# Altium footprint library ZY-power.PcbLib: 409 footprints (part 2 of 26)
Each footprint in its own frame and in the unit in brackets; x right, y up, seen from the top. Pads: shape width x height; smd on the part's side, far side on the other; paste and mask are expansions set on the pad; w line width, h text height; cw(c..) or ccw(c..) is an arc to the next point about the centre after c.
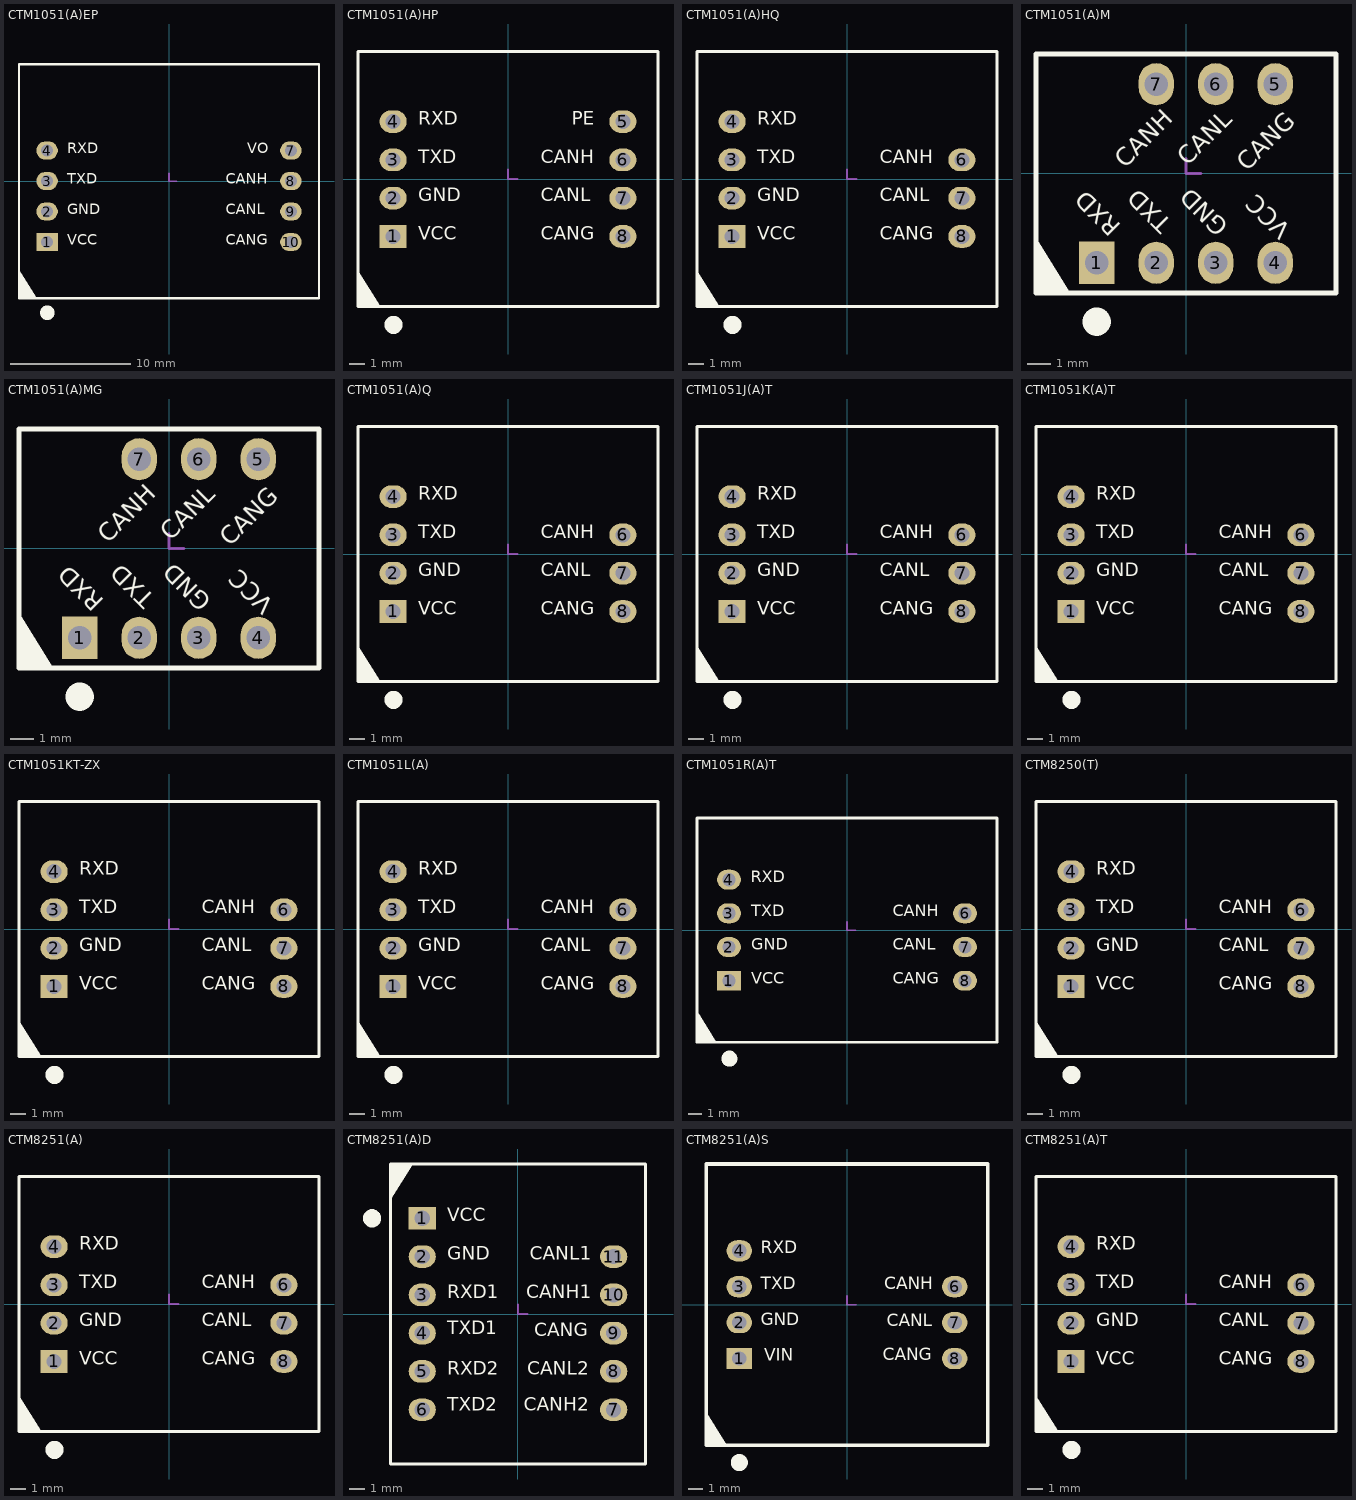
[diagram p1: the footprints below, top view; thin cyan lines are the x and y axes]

## CTM1051(A)EP [mm]
height 9.1
pads (8):
  rect 1.8x1.5 hole 1: 1(-10.16,-5.08)
  oval 1.8x1.5 hole 1: 2(-10.16,-2.54) 3(-10.16,0) 4(-10.16,2.54) 7(10.16,2.54) 8(10.16,0) 9(10.16,-2.54) 10(10.16,-5.08)
Top Overlay:
  circle w1: c-10.143,-10.975 r0.1
  region: -12.5,-7.42 -12.5,-9.75 -11.04,-9.75
  lines w0.2: -12.5,-9.75 12.5,-9.75 12.5,9.75 -12.5,9.75 -12.5,-9.75
  text "VO" at 6.509,2.032 h1.52
  text "CANG" at 4.729,-5.588 h1.52
  text "CANL" at 4.729,-3.048 h1.52
  text "CANH" at 4.729,-0.508 h1.52
  text "GND" at -8.479,-3.048 h1.52
  text "TXD" at -8.479,-0.508 h1.52
  text "RXD" at -8.479,2.032 h1.52
  text "VCC" at -8.478,-5.588 h1.52
Mechanical 15:
  lines w0.127: 0,0.635 0,0 0.635,0

## CTM1051(A)HP [mm]
height 7.1
pads (8):
  rect 1.8x1.5 hole 1: 1(-7.62,-3.81)
  oval 1.8x1.5 hole 1: 2(-7.62,-1.27) 3(-7.62,1.27) 4(-7.62,3.81) 5(7.62,3.81) 6(7.62,1.27) 7(7.62,-1.27) 8(7.62,-3.81)
Top Overlay:
  circle w1: c-7.593,-9.675 r0.1
  region: -9.95,-6.12 -9.95,-8.45 -8.49,-8.45
  lines w0.2: -9.95,-8.45 9.95,-8.45 9.95,8.45 -9.95,8.45 -9.95,-8.45
  text "PE" at 4.23,3.302 h1.52
  text "CANG" at 2.189,-4.318 h1.52
  text "CANL" at 2.189,-1.778 h1.52
  text "CANH" at 2.189,0.762 h1.52
  text "GND" at -5.939,-1.778 h1.52
  text "TXD" at -5.939,0.762 h1.52
  text "RXD" at -5.969,3.302 h1.52
  text "VCC" at -5.938,-4.318 h1.52
Mechanical 15:
  lines w0.127: 0,0.635 0,0 0.635,0
3D body "zhen01.stp": height 6.09, standoff -4.41, extent 7.37,1.02 7.87,1.52
3D body "zhen01.stp": height 6.09, standoff -4.41, extent 7.37,-1.52 7.87,-1.02
3D body "zhen01.stp": height 6.09, standoff -4.41, extent 7.37,-4.06 7.87,-3.56
3D body "zhen01.stp": height 6.09, standoff -4.41, extent -7.87,-4.06 -7.37,-3.56
3D body "zhen01.stp": height 6.09, standoff -4.41, extent -7.87,-1.52 -7.37,-1.02
3D body "zhen01.stp": height 6.09, standoff -4.41, extent -7.87,1.02 -7.37,1.52
3D body "zhen01.stp": height 6.09, standoff -4.41, extent -7.87,3.56 -7.37,4.06
3D body: height 7.1, standoff 0, extent -9.95,-8.45 9.95,8.45
3D body "zhen01.stp": height 6.09, standoff -4.41, extent 7.37,3.56 7.87,4.06

## CTM1051(A)HQ [mm]
height 7.1
pads (7):
  rect 1.8x1.5 hole 1: 1(-7.62,-3.81)
  oval 1.8x1.5 hole 1: 2(-7.62,-1.27) 3(-7.62,1.27) 4(-7.62,3.81) 6(7.62,1.27) 7(7.62,-1.27) 8(7.62,-3.81)
Top Overlay:
  circle w1: c-7.593,-9.675 r0.1
  region: -9.95,-6.12 -9.95,-8.45 -8.49,-8.45
  lines w0.2: -9.95,-8.45 9.95,-8.45 9.95,8.45 -9.95,8.45 -9.95,-8.45
  text "CANG" at 2.189,-4.318 h1.52
  text "CANL" at 2.189,-1.778 h1.52
  text "CANH" at 2.189,0.762 h1.52
  text "GND" at -5.939,-1.778 h1.52
  text "TXD" at -5.939,0.762 h1.52
  text "RXD" at -5.939,3.302 h1.52
  text "VCC" at -5.938,-4.318 h1.52
Mechanical 15:
  lines w0.127: 0,0.635 0,0 0.635,0

## CTM1051(A)M [mm]
height 7.7
pads (7):
  rect 1.5x1.8 hole 1: 1(-3.81,-3.81)
  oval 1.5x1.8 hole 1: 2(-1.27,-3.81) 3(1.27,-3.81) 4(3.81,-3.81) 5(3.81,3.81) 6(1.27,3.81) 7(-1.27,3.81)
Top Overlay:
  circle w1: c-3.81,-6.323 r0.1
  region: -6.4,-2.77 -6.4,-5.1 -4.94,-5.1
  lines w0.2: -6.4,-5.1 6.4,-5.1 6.4,5.1 -6.4,5.1 -6.4,-5.1
  text "VCC" at 4.699,-2.159 h1.27
  text "GND" at 2.032,-2.032 h1.27
  text "TXD" at -0.381,-1.905 h1.27
  text "RXD" at -2.54,-2.032 h1.27
  text "CANH" at -2.413,0 h1.27
  text "CANL" at 0.254,0.127 h1.27
  text "CANG" at 2.794,-0.127 h1.27
Mechanical 15:
  lines w0.127: 0,0.635 0,0 0.635,0
3D body "zhen01.stp": height 6.09, standoff -4.41, extent -1.52,3.56 -1.02,4.06
3D body "zhen01.stp": height 6.09, standoff -4.41, extent 1.02,3.56 1.52,4.06
3D body "zhen01.stp": height 6.09, standoff -4.41, extent 3.56,3.56 4.06,4.06
3D body "zhen01.stp": height 6.09, standoff -4.41, extent 3.56,-4.06 4.06,-3.56
3D body "zhen01.stp": height 6.09, standoff -4.41, extent 1.02,-4.06 1.52,-3.56
3D body "zhen01.stp": height 6.09, standoff -4.41, extent -1.52,-4.06 -1.02,-3.56
3D body "zhen01.stp": height 6.09, standoff -4.41, extent -4.06,-4.06 -3.56,-3.56
3D body: height 7.7, standoff 0, extent -6.4,-5.1 6.4,5.1

## CTM1051(A)MG [mm]
height 7.7
pads (7):
  rect 1.5x1.8 hole 1: 1(-3.81,-3.81)
  oval 1.5x1.8 hole 1: 2(-1.27,-3.81) 3(1.27,-3.81) 4(3.81,-3.81) 5(3.81,3.81) 6(1.27,3.81) 7(-1.27,3.81)
Top Overlay:
  circle w1: c-3.81,-6.323 r0.1
  region: -6.4,-2.77 -6.4,-5.1 -4.94,-5.1
  lines w0.2: -6.4,-5.1 6.4,-5.1 6.4,5.1 -6.4,5.1 -6.4,-5.1
  text "VCC" at 4.699,-2.159 h1.27
  text "GND" at 2.032,-2.032 h1.27
  text "TXD" at -0.381,-1.905 h1.27
  text "RXD" at -2.54,-2.032 h1.27
  text "CANH" at -2.413,0 h1.27
  text "CANL" at 0.254,0.127 h1.27
  text "CANG" at 2.794,-0.127 h1.27
Mechanical 15:
  lines w0.127: 0,0.635 0,0 0.635,0
3D body "zhen01.stp": height 6.09, standoff -4.41, extent -1.52,3.56 -1.02,4.06
3D body "zhen01.stp": height 6.09, standoff -4.41, extent 1.02,3.56 1.52,4.06
3D body "zhen01.stp": height 6.09, standoff -4.41, extent 3.56,3.56 4.06,4.06
3D body "zhen01.stp": height 6.09, standoff -4.41, extent 3.56,-4.06 4.06,-3.56
3D body "zhen01.stp": height 6.09, standoff -4.41, extent 1.02,-4.06 1.52,-3.56
3D body "zhen01.stp": height 6.09, standoff -4.41, extent -1.52,-4.06 -1.02,-3.56
3D body "zhen01.stp": height 6.09, standoff -4.41, extent -4.06,-4.06 -3.56,-3.56
3D body: height 7.7, standoff 0, extent -6.4,-5.1 6.4,5.1

## CTM1051(A)Q [mm]
height 7.1
pads (7):
  rect 1.8x1.5 hole 1: 1(-7.62,-3.81)
  oval 1.8x1.5 hole 1: 2(-7.62,-1.27) 3(-7.62,1.27) 4(-7.62,3.81) 6(7.62,1.27) 7(7.62,-1.27) 8(7.62,-3.81)
Top Overlay:
  circle w1: c-7.593,-9.673 r0.1
  region: -9.95,-6.12 -9.95,-8.45 -8.49,-8.45
  lines w0.2: -9.95,-8.45 9.95,-8.45 9.95,8.45 -9.95,8.45 -9.95,-8.45
  text "CANG" at 2.189,-4.318 h1.52
  text "CANL" at 2.189,-1.778 h1.52
  text "CANH" at 2.189,0.762 h1.52
  text "GND" at -5.939,-1.778 h1.52
  text "TXD" at -5.939,0.762 h1.52
  text "RXD" at -5.939,3.302 h1.52
  text "VCC" at -5.938,-4.318 h1.52
Mechanical 15:
  lines w0.127: 0,0.635 0,0 0.635,0

## CTM1051J(A)T [mm]
height 7.1
pads (7):
  rect 1.8x1.5 hole 1: 1(-7.62,-3.81)
  oval 1.8x1.5 hole 1: 2(-7.62,-1.27) 3(-7.62,1.27) 4(-7.62,3.81) 6(7.62,1.27) 7(7.62,-1.27) 8(7.62,-3.81)
Top Overlay:
  circle w1: c-7.593,-9.675 r0.1
  region: -9.95,-6.12 -9.95,-8.45 -8.49,-8.45
  lines w0.2: -9.95,-8.45 -9.95,8.45 9.95,8.45 9.95,-8.45 -9.95,-8.45
  text "VCC" at -5.938,-4.318 h1.52
  text "RXD" at -5.939,3.302 h1.52
  text "TXD" at -5.939,0.762 h1.52
  text "GND" at -5.939,-1.778 h1.52
  text "CANH" at 2.189,0.762 h1.52
  text "CANL" at 2.189,-1.778 h1.52
  text "CANG" at 2.189,-4.318 h1.52
Mechanical 15:
  lines w0.127: 0,0.635 0,0 0.635,0
3D body "zhen01.stp": height 6.09, standoff -4.41, extent 7.37,1.02 7.87,1.52
3D body "zhen01.stp": height 6.09, standoff -4.41, extent 7.37,-1.52 7.87,-1.02
3D body "zhen01.stp": height 6.09, standoff -4.41, extent 7.37,-4.06 7.87,-3.56
3D body "zhen01.stp": height 6.09, standoff -4.41, extent -7.87,-4.06 -7.37,-3.56
3D body "zhen01.stp": height 6.09, standoff -4.41, extent -7.87,-1.52 -7.37,-1.02
3D body "zhen01.stp": height 6.09, standoff -4.41, extent -7.87,1.02 -7.37,1.52
3D body "zhen01.stp": height 6.09, standoff -4.41, extent -7.87,3.56 -7.37,4.06
3D body: height 7.1, standoff 0, extent -9.95,-8.45 9.95,8.45

## CTM1051K(A)T [mm]
height 7.1
pads (7):
  rect 1.8x1.5 hole 1: 1(-7.62,-3.81)
  oval 1.8x1.5 hole 1: 2(-7.62,-1.27) 3(-7.62,1.27) 4(-7.62,3.81) 6(7.62,1.27) 7(7.62,-1.27) 8(7.62,-3.81)
Top Overlay:
  circle w1: c-7.593,-9.675 r0.1
  region: -9.95,-6.12 -9.95,-8.45 -8.49,-8.45
  lines w0.2: -9.95,-8.45 9.95,-8.45 9.95,8.45 -9.95,8.45 -9.95,-8.45
  text "CANG" at 2.189,-4.318 h1.52
  text "CANL" at 2.189,-1.778 h1.52
  text "CANH" at 2.189,0.762 h1.52
  text "GND" at -5.939,-1.778 h1.52
  text "TXD" at -5.939,0.762 h1.52
  text "RXD" at -5.939,3.302 h1.52
  text "VCC" at -5.938,-4.318 h1.52
Mechanical 15:
  lines w0.127: 0,0.635 0,0 0.635,0
3D body: height 7.1, standoff 0, extent -9.95,-8.45 9.95,8.45
3D body "zhen01.stp": height 6.09, standoff -4.41, extent -7.87,3.56 -7.37,4.06
3D body "zhen01.stp": height 6.09, standoff -4.41, extent -7.87,1.02 -7.37,1.52
3D body "zhen01.stp": height 6.09, standoff -4.41, extent -7.87,-1.52 -7.37,-1.02
3D body "zhen01.stp": height 6.09, standoff -4.41, extent -7.87,-4.06 -7.37,-3.56
3D body "zhen01.stp": height 6.09, standoff -4.41, extent 7.37,-4.06 7.87,-3.56
3D body "zhen01.stp": height 6.09, standoff -4.41, extent 7.37,-1.52 7.87,-1.02
3D body "zhen01.stp": height 6.09, standoff -4.41, extent 7.37,1.02 7.87,1.52

## CTM1051KT-ZX [mm]
height 7.1
pads (7):
  rect 1.8x1.5 hole 1: 1(-7.62,-3.81)
  oval 1.8x1.5 hole 1: 2(-7.62,-1.27) 3(-7.62,1.27) 4(-7.62,3.81) 6(7.62,1.27) 7(7.62,-1.27) 8(7.62,-3.81)
Top Overlay:
  circle w1: c-7.593,-9.675 r0.1
  region: -9.95,-6.12 -9.95,-8.45 -8.49,-8.45
  lines w0.2: -9.95,-8.45 -9.95,8.45 9.95,8.45 9.95,-8.45 -9.95,-8.45
  text "VCC" at -5.938,-4.318 h1.52
  text "RXD" at -5.939,3.302 h1.52
  text "TXD" at -5.939,0.762 h1.52
  text "GND" at -5.939,-1.778 h1.52
  text "CANH" at 2.189,0.762 h1.52
  text "CANL" at 2.189,-1.778 h1.52
  text "CANG" at 2.189,-4.318 h1.52
Mechanical 15:
  lines w0.127: 0,0.635 0,0 0.635,0
3D body "zhen01.stp": height 6.09, standoff -4.41, extent 7.37,1.02 7.87,1.52
3D body "zhen01.stp": height 6.09, standoff -4.41, extent 7.37,-1.52 7.87,-1.02
3D body "zhen01.stp": height 6.09, standoff -4.41, extent 7.37,-4.06 7.87,-3.56
3D body "zhen01.stp": height 6.09, standoff -4.41, extent -7.87,-4.06 -7.37,-3.56
3D body "zhen01.stp": height 6.09, standoff -4.41, extent -7.87,-1.52 -7.37,-1.02
3D body "zhen01.stp": height 6.09, standoff -4.41, extent -7.87,1.02 -7.37,1.52
3D body "zhen01.stp": height 6.09, standoff -4.41, extent -7.87,3.56 -7.37,4.06
3D body: height 7.1, standoff 0, extent -9.95,-8.45 9.95,8.45

## CTM1051L(A) [mm]
height 7.1
pads (7):
  rect 1.8x1.5 hole 1: 1(-7.62,-3.81)
  oval 1.8x1.5 hole 1: 2(-7.62,-1.27) 3(-7.62,1.27) 4(-7.62,3.81) 6(7.62,1.27) 7(7.62,-1.27) 8(7.62,-3.81)
Top Overlay:
  circle w1: c-7.593,-9.675 r0.1
  region: -9.95,-6.12 -9.95,-8.45 -8.49,-8.45
  lines w0.2: -9.95,-8.45 -9.95,8.45 9.95,8.45 9.95,-8.45 -9.95,-8.45
  text "VCC" at -5.938,-4.318 h1.52
  text "RXD" at -5.939,3.302 h1.52
  text "TXD" at -5.939,0.762 h1.52
  text "GND" at -5.939,-1.778 h1.52
  text "CANH" at 2.189,0.762 h1.52
  text "CANL" at 2.189,-1.778 h1.52
  text "CANG" at 2.189,-4.318 h1.52
Mechanical 15:
  lines w0.127: 0,0.635 0,0 0.635,0
3D body: height 7.1, standoff 0, extent -9.95,-8.45 9.95,8.45
3D body "zhen01.stp": height 6.09, standoff -4.41, extent -7.87,3.56 -7.37,4.06
3D body "zhen01.stp": height 6.09, standoff -4.41, extent -7.87,1.02 -7.37,1.52
3D body "zhen01.stp": height 6.09, standoff -4.41, extent -7.87,-1.52 -7.37,-1.02
3D body "zhen01.stp": height 6.09, standoff -4.41, extent -7.87,-4.06 -7.37,-3.56
3D body "zhen01.stp": height 6.09, standoff -4.41, extent 7.37,-4.06 7.87,-3.56
3D body "zhen01.stp": height 6.09, standoff -4.41, extent 7.37,-1.52 7.87,-1.02
3D body "zhen01.stp": height 6.09, standoff -4.41, extent 7.37,1.02 7.87,1.52

## CTM1051R(A)T [mm]
height 12.8
pads (7):
  rect 1.8x1.5 hole 1: 1(-8.89,-3.81)
  oval 1.8x1.5 hole 1: 2(-8.89,-1.27) 3(-8.89,1.27) 4(-8.89,3.81) 6(8.89,1.27) 7(8.89,-1.27) 8(8.89,-3.81)
Top Overlay:
  circle w1: c-8.863,-9.675 r0.1
  region: -11.3,-6.12 -11.3,-8.45 -9.84,-8.45
  lines w0.2: -11.3,-8.45 11.3,-8.45 11.3,8.45 -11.3,8.45 -11.3,-8.45
  text "CANG" at 3.459,-4.318 h1.52
  text "CANL" at 3.459,-1.778 h1.52
  text "CANH" at 3.459,0.762 h1.52
  text "GND" at -7.209,-1.778 h1.52
  text "TXD" at -7.209,0.745 h1.52
  text "RXD" at -7.239,3.302 h1.52
  text "VCC" at -7.208,-4.318 h1.52
Mechanical 15:
  lines w0.127: 0,0.635 0,0 0.635,0
3D body: height 12.8, standoff 0, extent -11.3,-8.45 11.3,8.45
3D body "zhen01.stp": height 6.09, standoff -4.41, extent -9.14,-4.06 -8.64,-3.56
3D body "zhen01.stp": height 6.09, standoff -4.41, extent -9.14,-1.52 -8.64,-1.02
3D body "zhen01.stp": height 6.09, standoff -4.41, extent -9.14,1.02 -8.64,1.52
3D body "zhen01.stp": height 6.09, standoff -4.41, extent -9.14,3.56 -8.64,4.06
3D body "zhen01.stp": height 6.09, standoff -4.41, extent 8.64,-4.06 9.14,-3.56
3D body "zhen01.stp": height 6.09, standoff -4.41, extent 8.64,-1.52 9.14,-1.02
3D body "zhen01.stp": height 6.09, standoff -4.41, extent 8.64,1.02 9.14,1.52

## CTM8250(T) [mm]
height 7.1
pads (7):
  rect 1.8x1.5 hole 1: 1(-7.62,-3.81)
  oval 1.8x1.5 hole 1: 2(-7.62,-1.27) 3(-7.62,1.27) 4(-7.62,3.81) 6(7.62,1.27) 7(7.62,-1.27) 8(7.62,-3.81)
Top Overlay:
  circle w1: c-7.593,-9.675 r0.1
  region: -9.95,-6.12 -9.95,-8.45 -8.49,-8.45
  lines w0.2: -9.95,-8.45 9.95,-8.45 9.95,8.45 -9.95,8.45 -9.95,-8.45
  text "CANG" at 2.189,-4.318 h1.52
  text "CANL" at 2.189,-1.778 h1.52
  text "CANH" at 2.189,0.762 h1.52
  text "GND" at -5.939,-1.778 h1.52
  text "TXD" at -5.939,0.762 h1.52
  text "RXD" at -5.939,3.302 h1.52
  text "VCC" at -5.938,-4.318 h1.52
Mechanical 15:
  lines w0.127: 0,0.635 0,0 0.635,0

## CTM8251(A) [mm]
height 7.1
pads (7):
  rect 1.8x1.5 hole 1: 1(-7.62,-3.81)
  oval 1.8x1.5 hole 1: 2(-7.62,-1.27) 3(-7.62,1.27) 4(-7.62,3.81) 6(7.62,1.27) 7(7.62,-1.27) 8(7.62,-3.81)
Top Overlay:
  circle w1: c-7.593,-9.673 r0.1
  region: -9.95,-6.12 -9.95,-8.45 -8.49,-8.45
  lines w0.2: -9.95,-8.45 9.95,-8.45 9.95,8.45 -9.95,8.45 -9.95,-8.45
  text "CANG" at 2.189,-4.318 h1.52
  text "CANL" at 2.189,-1.778 h1.52
  text "CANH" at 2.189,0.762 h1.52
  text "GND" at -5.939,-1.778 h1.52
  text "TXD" at -5.939,0.762 h1.52
  text "RXD" at -5.969,3.302 h1.52
  text "VCC" at -5.938,-4.318 h1.52
Mechanical 15:
  lines w0.127: 0,0.635 0,0 0.635,0

## CTM8251(A)D [mm]
height 7.05
pads (11):
  rect 1.8x1.5 hole 1: 1(-6.35,6.35)
  oval 1.8x1.5 hole 1: 2(-6.35,3.81) 3(-6.35,1.27) 4(-6.35,-1.27) 5(-6.35,-3.81) 6(-6.35,-6.35) 7(6.35,-6.35) 8(6.35,-3.81) 9(6.35,-1.27) 10(6.35,1.27) 11(6.35,3.81)
Top Overlay:
  circle w1: c-9.673,6.35 r0.1
  region: -8.45,7.62 -8.45,9.95 -6.99,9.95
  lines w0.2: -8.45,-9.95 -8.45,9.95 8.45,9.95 8.45,-9.95 -8.45,-9.95
  text "RXD2" at -4.699,-4.318 h1.52
  text "TXD2" at -4.699,-6.731 h1.52
  text "CANH2" at 0.381,-6.731 h1.52
  text "CANL2" at 0.607,-4.318 h1.52
  text "TXD1" at -4.699,-1.651 h1.52
  text "RXD1" at -4.699,0.762 h1.52
  text "GND" at -4.699,3.302 h1.52
  text "VCC" at -4.698,5.842 h1.52
  text "CANL1" at 0.785,3.302 h1.52
  text "CANH1" at 0.559,0.762 h1.52
  text "CANG" at 1.076,-1.778 h1.52
Mechanical 15:
  lines w0.127: 0,0.635 0,0 0.635,0

## CTM8251(A)S [mm]
height 5
pads (7):
  rect 1.8x1.5 hole 1: 1(-7.62,-3.81)
  oval 1.8x1.5 hole 1: 2(-7.62,-1.27) 3(-7.62,1.27) 4(-7.62,3.81) 6(7.62,1.27) 7(7.62,-1.27) 8(7.62,-3.81)
Top Overlay:
  circle w1: c-7.62,-11.173 r0.1
  region: -9.95,-7.62 -9.95,-9.95 -8.49,-9.95
  lines w0.254: -9.95,-9.95 9.95,-9.95 9.95,9.95 -9.95,9.95 -9.95,-9.95
  text "VIN" at -5.867,-4.293 h1.52
  text "GND" at -6.096,-1.761 h1.52
  text "TXD" at -6.096,0.77 h1.52
  text "RXD" at -6.096,3.302 h1.52
  text "CANH" at 2.641,0.762 h1.52
  text "CANL" at 2.806,-1.854 h1.52
  text "CANG" at 2.54,-4.267 h1.52
Mechanical 15:
  lines w0.127: 0,0.635 0,0 0.635,0

## CTM8251(A)T [mm]
height 7.1
pads (7):
  rect 1.8x1.5 hole 1: 1(-7.62,-3.81)
  oval 1.8x1.5 hole 1: 2(-7.62,-1.27) 3(-7.62,1.27) 4(-7.62,3.81) 6(7.62,1.27) 7(7.62,-1.27) 8(7.62,-3.81)
Top Overlay:
  circle w1: c-7.593,-9.675 r0.1
  region: -9.95,-6.223 -9.95,-8.45 -8.49,-8.45 -9.838,-6.298
  lines w0.2: -9.95,-8.45 9.95,-8.45 9.95,8.45 -9.95,8.45 -9.95,-8.45
  text "CANG" at 2.189,-4.318 h1.52
  text "CANL" at 2.189,-1.778 h1.52
  text "CANH" at 2.189,0.762 h1.52
  text "GND" at -5.939,-1.778 h1.52
  text "TXD" at -5.939,0.762 h1.52
  text "RXD" at -5.969,3.302 h1.52
  text "VCC" at -5.938,-4.318 h1.52
Mechanical 15:
  lines w0.127: 0,0.635 0,0 0.635,0
3D body "zhen01.stp": height 6.09, standoff -4.41, extent 7.37,1.02 7.87,1.52
3D body "zhen01.stp": height 6.09, standoff -4.41, extent 7.37,-1.52 7.87,-1.02
3D body "zhen01.stp": height 6.09, standoff -4.41, extent 7.37,-4.06 7.87,-3.56
3D body "zhen01.stp": height 6.09, standoff -4.41, extent -7.87,-4.06 -7.37,-3.56
3D body "zhen01.stp": height 6.09, standoff -4.41, extent -7.87,-1.52 -7.37,-1.02
3D body "zhen01.stp": height 6.09, standoff -4.41, extent -7.87,1.02 -7.37,1.52
3D body "zhen01.stp": height 6.09, standoff -4.41, extent -7.87,3.56 -7.37,4.06
3D body: height 7.1, standoff 0, extent -9.95,-8.45 9.95,8.45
